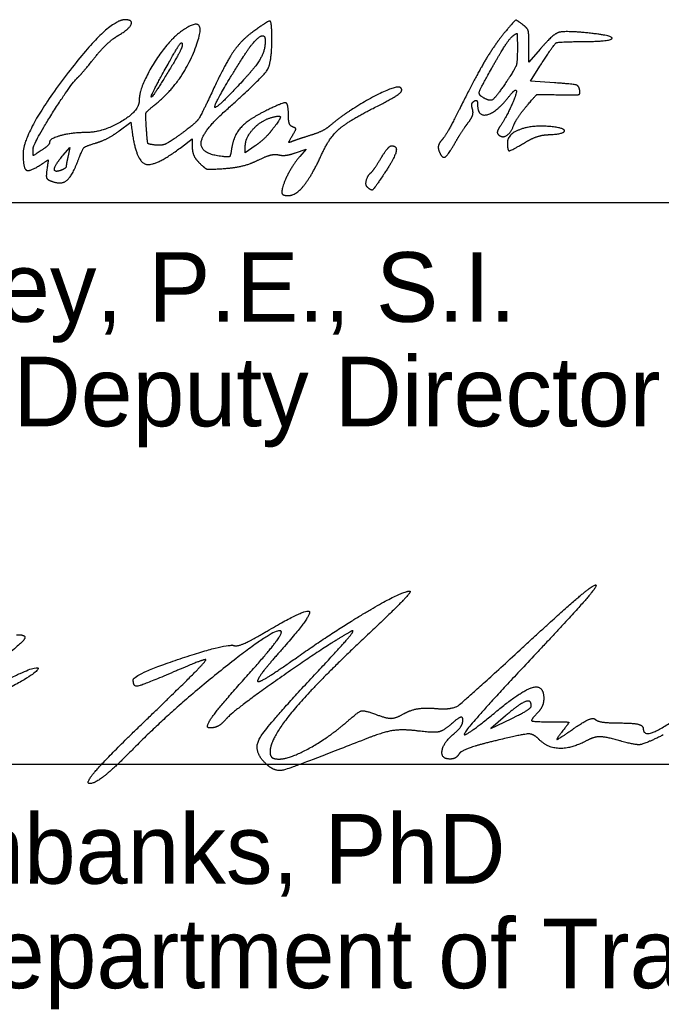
# Model space of a CAD drawing. Extents: x 0 to 40.2, y 0 to 22.
# Drawn here: x 25.477 to 26.766, y 6.637 to 8.626 of the extents above; entities that cross this region are included whole.
import ezdxf

# ---------------------------------------------------------------- set-up
doc = ezdxf.new("R2010")
doc.units = 0
doc.layers.add('GM_X_Adjacent_County', color=7, linetype='Continuous')
doc.layers.add('GM_X_Adjacent_County_Text', color=7, linetype='Continuous')

msp = doc.modelspace()

# ---------------------------------------------------------------- linework, layer by layer
at = {"layer": 'GM_X_Adjacent_County'}
for p, q in [((24.5279, 8.259), (28.0279, 8.259)), ((24.5279, 7.1296), (28.0279, 7.1296))]:
    msp.add_line(p, q, dxfattribs=at)
at = {"layer": 'GM_X_Adjacent_County_Text'}
for p, q in [((26.1747, 8.2901), (26.1747, 8.2901)), ((26.5045, 7.2468), (26.5045, 7.2468)), ((25.7273, 7.2158), (25.7273, 7.2158))]:
    msp.add_line(p, q, dxfattribs=at)
for points in [[(26.522, 8.5668), (26.4998, 8.5409), (26.4998, 8.574)], [(26.5512, 8.4994), (26.5026, 8.5028), (26.5218, 8.5328)], [(25.6766, 8.4029), (25.6998, 8.4201), (25.7018, 8.4048)], [(25.8015, 8.3703), (25.8232, 8.3868), (25.8232, 8.3698)], [(25.9495, 8.3726), (25.9298, 8.3585), (25.9298, 8.3722)], [(25.5637, 8.3537), (25.5775, 8.3694), (25.5738, 8.3528)], [(26.0309, 8.3588), (26.0523, 8.3663), (26.0391, 8.3512)], [(26.4527, 7.2271), (26.4232, 7.2015), (26.4638, 7.2212)]]:
    msp.add_lwpolyline(points, dxfattribs=at)
for points in [[(25.6877, 8.6261), (25.6543, 8.6261), (25.4832, 8.4004), (25.4832, 8.3563)], [(25.6744, 8.5944), (25.6964, 8.6074), (25.7043, 8.6261), (25.6877, 8.6261)], [(25.7461, 8.4537), (25.8029, 8.4983), (25.8571, 8.642), (25.8029, 8.604)], [(25.9832, 8.5882), (25.9832, 8.6225), (25.976, 8.6247), (25.9433, 8.6006)], [(26.4865, 8.617), (26.4742, 8.6261), (26.4717, 8.6252), (26.4546, 8.6048)], [(26.4998, 8.574), (26.4998, 8.5994), (26.4967, 8.6095), (26.4865, 8.617)], [(25.6261, 8.5487), (25.6405, 8.5666), (25.6622, 8.5872), (25.6744, 8.5944)], [(25.8029, 8.604), (25.7737, 8.5836), (25.7165, 8.4904), (25.7165, 8.4635)], [(25.9433, 8.6006), (25.9195, 8.583), (25.8867, 8.5329), (25.8575, 8.4694)], [(25.926, 8.552), (25.9448, 8.5818), (25.9698, 8.5999), (25.9698, 8.5838)], [(26.4546, 8.6048), (26.4319, 8.5778), (26.3931, 8.5128), (26.3599, 8.4461)], [(26.4261, 8.5307), (26.4427, 8.5602), (26.4608, 8.588), (26.4664, 8.5927)], [(26.4664, 8.5927), (26.4752, 8.6), (26.4765, 8.5968), (26.4765, 8.5677)], [(26.6182, 8.5996), (26.5705, 8.6044), (26.5475, 8.5966), (26.522, 8.5668)], [(26.6104, 8.5824), (26.6641, 8.5828), (26.6693, 8.5943), (26.6182, 8.5996)], [(25.763, 8.5161), (25.7898, 8.5649), (25.8032, 8.5847), (25.8032, 8.5755)], [(25.8032, 8.5755), (25.8032, 8.5717), (25.7925, 8.5508), (25.7794, 8.529)], [(25.8904, 8.4438), (25.9641, 8.5096), (25.9832, 8.5393), (25.9832, 8.5882)], [(25.9698, 8.5838), (25.9698, 8.5658), (25.9531, 8.5346), (25.9295, 8.5087)], [(26.5218, 8.5328), (26.5503, 8.5775), (26.5583, 8.582), (26.6104, 8.5824)], [(25.9295, 8.5087), (25.869, 8.4424), (25.8676, 8.4595), (25.926, 8.552)], [(26.4765, 8.5677), (26.4765, 8.5411), (26.4721, 8.5277), (26.4548, 8.5019)], [(25.5959, 8.5128), (25.598, 8.5146), (25.6116, 8.5308), (25.6261, 8.5487)], [(25.5032, 8.3657), (25.5032, 8.3765), (25.5814, 8.5007), (25.5959, 8.5128)], [(25.7794, 8.529), (25.7473, 8.4755), (25.7356, 8.4663), (25.763, 8.5161)], [(26.4046, 8.4716), (26.3981, 8.4758), (26.4033, 8.49), (26.4261, 8.5307)], [(26.4548, 8.5019), (26.4329, 8.4692), (26.4202, 8.4616), (26.4046, 8.4716)], [(26.6017, 8.4855), (26.6002, 8.4937), (26.5885, 8.4969), (26.5512, 8.4994)], [(26.2422, 8.4893), (26.2349, 8.4966), (26.1353, 8.4433), (26.0998, 8.4131)], [(26.1865, 8.4481), (26.2281, 8.4692), (26.2477, 8.4837), (26.2422, 8.4893)], [(26.474, 8.4841), (26.477, 8.4812), (26.4536, 8.4288), (26.4415, 8.4114)], [(26.4588, 8.4708), (26.4657, 8.4796), (26.4725, 8.4856), (26.474, 8.4841)], [(26.4952, 8.4528), (26.5144, 8.4753), (26.5167, 8.4761), (26.5594, 8.4755)], [(26.5594, 8.4755), (26.5966, 8.4749), (26.6034, 8.4766), (26.6017, 8.4855)], [(25.7165, 8.4635), (25.7165, 8.4427), (25.6436, 8.3995), (25.6085, 8.3994)], [(25.7311, 8.4082), (25.7293, 8.4359), (25.7314, 8.442), (25.7461, 8.4537)], [(25.8575, 8.4694), (25.8403, 8.4323), (25.829, 8.4176), (25.8016, 8.3974)], [(26.0165, 8.4328), (26.0165, 8.4583), (26.0056, 8.4604), (25.9686, 8.4419)], [(26.3863, 8.4466), (26.3843, 8.453), (26.3857, 8.4602), (26.3896, 8.4626)], [(26.3896, 8.4626), (26.3934, 8.465), (26.3965, 8.4621), (26.3965, 8.4563)], [(26.3965, 8.4563), (26.3965, 8.4309), (26.4343, 8.4397), (26.4588, 8.4708)], [(26.4694, 8.4143), (26.4727, 8.4226), (26.4843, 8.4399), (26.4952, 8.4528)], [(25.8832, 8.3513), (25.8393, 8.3563), (25.8428, 8.4013), (25.8904, 8.4438)], [(25.9686, 8.4419), (25.9343, 8.4248), (25.9057, 8.3921), (25.9021, 8.3661)], [(25.9815, 8.4294), (26.0001, 8.4347), (26.0006, 8.4264), (25.9829, 8.4039)], [(26.0248, 8.4109), (26.0202, 8.4125), (26.0165, 8.4224), (26.0165, 8.4328)], [(26.0842, 8.3575), (26.0984, 8.3889), (26.1367, 8.4228), (26.1865, 8.4481)], [(26.3599, 8.4461), (26.3462, 8.4186), (26.3305, 8.391), (26.3249, 8.3847)], [(26.3773, 8.4187), (26.3843, 8.4276), (26.3884, 8.4401), (26.3863, 8.4466)], [(25.9298, 8.3722), (25.9298, 8.389), (25.961, 8.4235), (25.9815, 8.4294)], [(26.0998, 8.4131), (26.0925, 8.4068), (26.0745, 8.398), (26.0598, 8.3935)], [(26.3519, 8.3797), (26.3589, 8.3922), (26.3703, 8.4098), (26.3773, 8.4187)], [(26.4381, 8.3956), (26.4457, 8.388), (26.4631, 8.3983), (26.4694, 8.4143)], [(26.5404, 8.4116), (26.5048, 8.4145), (26.4565, 8.3956), (26.4565, 8.3789)], [(25.6085, 8.3994), (25.5809, 8.3993), (25.5365, 8.3873), (25.5365, 8.3799)], [(25.6288, 8.3783), (25.6423, 8.3824), (25.6638, 8.3934), (25.6766, 8.4029)], [(25.7018, 8.4048), (25.7098, 8.3426), (25.7479, 8.3295), (25.8015, 8.3703)], [(25.7502, 8.3741), (25.7349, 8.3759), (25.733, 8.3794), (25.7311, 8.4082)], [(25.8016, 8.3974), (25.7786, 8.3805), (25.7616, 8.3728), (25.7502, 8.3741)], [(25.9829, 8.4039), (25.9754, 8.3944), (25.9604, 8.3803), (25.9495, 8.3726)], [(26.0243, 8.3816), (26.017, 8.3786), (26.017, 8.3805), (26.0243, 8.3929)], [(26.0243, 8.3929), (26.0313, 8.4047), (26.0314, 8.4085), (26.0248, 8.4109)], [(26.0598, 8.3935), (26.0452, 8.3889), (26.0292, 8.3836), (26.0243, 8.3816)], [(26.4415, 8.4114), (26.4372, 8.4052), (26.4356, 8.3981), (26.4381, 8.3956)], [(26.493, 8.3802), (26.5062, 8.388), (26.527, 8.3948), (26.5392, 8.3952)], [(26.5392, 8.3952), (26.5707, 8.3965), (26.5716, 8.409), (26.5404, 8.4116)], [(25.5365, 8.3799), (25.5365, 8.3768), (25.529, 8.3694), (25.5198, 8.3634)], [(25.593, 8.3414), (25.6024, 8.366), (25.6085, 8.3722), (25.6288, 8.3783)], [(26.2024, 8.3478), (26.2107, 8.3615), (26.2203, 8.3728), (26.2237, 8.3728)], [(26.2237, 8.3728), (26.2359, 8.3728), (26.2294, 8.3477), (26.2092, 8.3172)], [(26.3249, 8.3847), (26.3194, 8.3784), (26.3167, 8.3684), (26.319, 8.3625)], [(26.319, 8.3625), (26.325, 8.347), (26.3372, 8.3535), (26.3519, 8.3797)], [(26.4565, 8.3789), (26.4565, 8.3625), (26.4635, 8.3628), (26.493, 8.3802)], [(25.4832, 8.3563), (25.4832, 8.328), (25.4962, 8.32), (25.5186, 8.3347)], [(25.5198, 8.3634), (25.504, 8.353), (25.5032, 8.3531), (25.5032, 8.3657)], [(25.5598, 8.3237), (25.5452, 8.3181), (25.5474, 8.3352), (25.5637, 8.3537)], [(25.5738, 8.3528), (25.5717, 8.3436), (25.57, 8.3342), (25.5699, 8.3318)], [(25.8232, 8.3698), (25.8232, 8.3604), (25.8295, 8.3464), (25.8372, 8.3387)], [(25.9021, 8.3661), (25.9002, 8.3527), (25.8965, 8.3498), (25.8832, 8.3513)], [(25.9555, 8.3441), (25.971, 8.3517), (25.9895, 8.3565), (25.9966, 8.3547)], [(25.9966, 8.3547), (26.0036, 8.3528), (26.0191, 8.3547), (26.0309, 8.3588)], [(26.0165, 8.2728), (26.0315, 8.2728), (26.0646, 8.3142), (26.0842, 8.3575)], [(25.5186, 8.3347), (25.5336, 8.3445), (25.5339, 8.3442), (25.5312, 8.3255)], [(25.5395, 8.302), (25.5593, 8.2944), (25.5812, 8.3105), (25.593, 8.3414)], [(25.8372, 8.3387), (25.8491, 8.3268), (25.8573, 8.325), (25.8893, 8.3273)], [(25.8893, 8.3273), (25.9102, 8.3289), (25.94, 8.3364), (25.9555, 8.3441)], [(26.0391, 8.3512), (26.0256, 8.3357), (26.0032, 8.2908), (26.0032, 8.2792)], [(26.183, 8.3194), (26.1853, 8.3213), (26.194, 8.334), (26.2024, 8.3478)], [(25.5312, 8.3255), (25.5292, 8.3118), (25.5316, 8.305), (25.5395, 8.302)], [(25.5699, 8.3318), (25.5699, 8.3295), (25.5653, 8.3258), (25.5598, 8.3237)], [(26.1747, 8.2901), (26.1705, 8.2943), (26.176, 8.3138), (26.183, 8.3194)], [(26.2092, 8.3172), (26.1891, 8.2868), (26.1829, 8.282), (26.1747, 8.2901)], [(26.0032, 8.2792), (26.0032, 8.2757), (26.0091, 8.2728), (26.0165, 8.2728)], [(26.0326, 7.3439), (26.1131, 7.4005), (26.2445, 7.4777), (26.2602, 7.4777)], [(26.2602, 7.4777), (26.265, 7.4777), (26.2237, 7.4351), (26.1684, 7.383)], [(26.4869, 7.3643), (26.5619, 7.4334), (26.6279, 7.49), (26.6336, 7.4901)], [(26.6336, 7.4901), (26.6394, 7.4902), (26.5873, 7.43), (26.518, 7.3564)], [(25.9736, 7.3974), (26.0524, 7.4436), (26.0646, 7.4303), (26.0054, 7.363)], [(26.0017, 7.3972), (25.9921, 7.4068), (25.7824, 7.2398), (25.7045, 7.1606)], [(26.0768, 7.3178), (26.123, 7.367), (26.1523, 7.4025), (26.142, 7.3967)], [(25.4701, 7.3901), (25.495, 7.3906), (25.4716, 7.365), (25.3857, 7.2977)], [(26.142, 7.3967), (26.0929, 7.3689), (25.9046, 7.2367), (25.8914, 7.2208)], [(25.908, 7.3682), (25.9136, 7.3664), (25.9431, 7.3795), (25.9736, 7.3974)], [(25.9239, 7.2968), (25.9702, 7.3485), (26.0052, 7.3937), (26.0017, 7.3972)], [(26.1684, 7.383), (26.0687, 7.2893), (25.9795, 7.1812), (25.9795, 7.1542)], [(25.7047, 7.2996), (25.7049, 7.3102), (25.8923, 7.3733), (25.908, 7.3682)], [(26.0054, 7.363), (25.9774, 7.3312), (25.9545, 7.3015), (25.9545, 7.2971)], [(26.3119, 7.2419), (26.3453, 7.2391), (26.3688, 7.2555), (26.4869, 7.3643)], [(25.7273, 7.2158), (25.7983, 7.2842), (25.8537, 7.3402), (25.8502, 7.3402)], [(25.8502, 7.3402), (25.8468, 7.3402), (25.8178, 7.329), (25.7857, 7.3152)], [(25.9545, 7.2971), (25.9545, 7.2926), (25.9896, 7.3137), (26.0326, 7.3439)], [(26.518, 7.3564), (26.3885, 7.2189), (26.3564, 7.1716), (26.4386, 7.2393)], [(25.3555, 7.2448), (25.3759, 7.2627), (25.5079, 7.3284), (25.5131, 7.3233)], [(25.5131, 7.3233), (25.5193, 7.3171), (25.3767, 7.2402), (25.359, 7.2402)], [(25.7857, 7.3152), (25.7231, 7.2884), (25.7044, 7.2848), (25.7047, 7.2996)], [(25.9697, 7.1322), (25.9445, 7.1574), (25.9734, 7.2075), (26.0768, 7.3178)], [(26.7295, 7.2012), (26.7295, 7.1784), (26.8248, 7.2399), (26.8951, 7.3081)], [(25.8581, 7.2027), (25.8478, 7.2027), (25.8767, 7.244), (25.9239, 7.2968)], [(26.4386, 7.2393), (26.487, 7.2792), (26.5295, 7.2896), (26.5295, 7.2615)], [(26.5295, 7.2615), (26.5295, 7.2526), (26.5227, 7.2385), (26.5145, 7.2302)], [(26.2489, 7.2315), (26.2623, 7.239), (26.2906, 7.2437), (26.3119, 7.2419)], [(26.5045, 7.2468), (26.5045, 7.2603), (26.4804, 7.2511), (26.4527, 7.2271)], [(26.4638, 7.2212), (26.4862, 7.232), (26.5045, 7.2436), (26.5045, 7.2468)], [(25.8914, 7.2208), (25.8831, 7.2108), (25.8682, 7.2027), (25.8581, 7.2027)], [(26.137, 7.2178), (26.1573, 7.2358), (26.1701, 7.2384), (26.1939, 7.2294)], [(26.1939, 7.2294), (26.2141, 7.2217), (26.2329, 7.2224), (26.2489, 7.2315)], [(26.367, 7.2187), (26.367, 7.2258), (26.3568, 7.2224), (26.3444, 7.2112)], [(26.5145, 7.2302), (26.5028, 7.2186), (26.5087, 7.2152), (26.541, 7.2152)], [(26.5871, 7.1997), (26.6085, 7.2147), (26.6293, 7.2238), (26.6332, 7.2199)], [(26.6332, 7.2199), (26.6371, 7.216), (26.6604, 7.2127), (26.6849, 7.2127)], [(25.617, 7.0909), (25.6067, 7.0911), (25.6563, 7.1473), (25.7273, 7.2158)], [(25.9975, 7.1402), (26.0192, 7.1402), (26.1006, 7.1855), (26.137, 7.2178)], [(26.3444, 7.2112), (26.3287, 7.197), (26.3075, 7.1926), (26.2749, 7.1968)], [(26.3482, 7.1902), (26.3585, 7.1988), (26.367, 7.2116), (26.367, 7.2187)], [(26.541, 7.2152), (26.5785, 7.2152), (26.5809, 7.2132), (26.5654, 7.1939)], [(26.5654, 7.1939), (26.5533, 7.1789), (26.5598, 7.1806), (26.5871, 7.1997)], [(26.6849, 7.2127), (26.7094, 7.2127), (26.7295, 7.2076), (26.7295, 7.2012)], [(26.1693, 7.1796), (26.0233, 7.122), (25.9882, 7.1136), (25.9697, 7.1322)], [(26.2749, 7.1968), (26.2457, 7.2005), (26.2058, 7.1941), (26.1693, 7.1796)], [(26.3412, 7.1402), (26.3229, 7.1402), (26.3274, 7.173), (26.3482, 7.1902)], [(26.5199, 7.1798), (26.5088, 7.191), (26.4887, 7.1905), (26.4355, 7.1777)], [(26.6162, 7.1773), (26.5854, 7.1609), (26.5376, 7.1621), (26.5199, 7.1798)], [(26.6807, 7.1774), (26.6538, 7.1851), (26.6307, 7.1851), (26.6162, 7.1773)], [(26.7698, 7.1887), (26.7324, 7.1703), (26.7138, 7.1679), (26.6807, 7.1774)], [(25.7045, 7.1606), (25.6667, 7.1221), (25.6273, 7.0908), (25.617, 7.0909)], [(26.4355, 7.1777), (26.3972, 7.1685), (26.3629, 7.1563), (26.3594, 7.1506)], [(25.9795, 7.1542), (25.9795, 7.1465), (25.9876, 7.1402), (25.9975, 7.1402)], [(26.3594, 7.1506), (26.3559, 7.1449), (26.3477, 7.1402), (26.3412, 7.1402)]]:
    msp.add_open_spline(points, degree=2, dxfattribs=at)

# ---------------------------------------------------------------- texts
for s, p in [('Pat McColley, P.E., S.I.', (24.5279, 8.019)), ('District       Deputy Director', (24.5279, 7.809)), ('Jack Marchbanks, PhD', (24.5279, 6.8896)), ('Director, Department of Transportation', (24.5279, 6.6796))]:
    msp.add_text(s, height=0.14, dxfattribs=at).set_placement(p)

doc.saveas('drawing.dxf')
